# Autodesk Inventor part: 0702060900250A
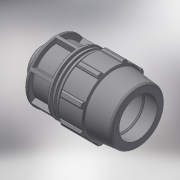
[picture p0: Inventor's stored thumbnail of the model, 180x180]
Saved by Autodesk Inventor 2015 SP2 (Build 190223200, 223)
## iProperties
Created: 2017-02
Part Number: 0702060900250A
Material: Generic
Description: PLASSON MALE ADAPTOR 90-2.1/2"
Document SubType Name: Modeling
Designer: KIM
Mass: 964.158 g
Surface Area: 1468.9 cm^2
Volume: 964.158 cm^3
Density: 1 g/cm^3
Appearance: Default
Author: KIM
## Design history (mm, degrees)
derived "87020.ipt"
feature "Solid1::87020.ipt"
tag "TaggingFeature1"
body "Solid1"
other parameters: "d4" = 32.71429, "d5" = 57.25, "d7" = 152, "d8" = 114, "d9" = 32.71429, "d11" = 6.54286, "d12" = 121.6, "d13" = 120 deg, "d14" = 117, "d15" = 6 deg, "d16" = 136.8, "d18" = 4.5, "d19" = 35 deg, "d20" = 17.5 deg, "d21" = 141.36, "d23" = 0, "d25" = 360 deg, "d27" = 3.04, "d34" = 7.6, "d36" = 0, "d42" = 68.7, "d43" = 4.56, "d46" = 2.7, "d51" = 229, "d52" = 29, "d53" = 1.8, "d55" = 360 deg, "d57" = 75.184, "d58" = 52.6288, "d59" = 45.8, "d61" = 134.064, "d62" = 3.03286, "d63" = 3.03286, "d66" = 6.06571, "E_" = 152, "H_" = 229, "l_2" = 29, "R_" = 75.184, "d60" = 15.16429
